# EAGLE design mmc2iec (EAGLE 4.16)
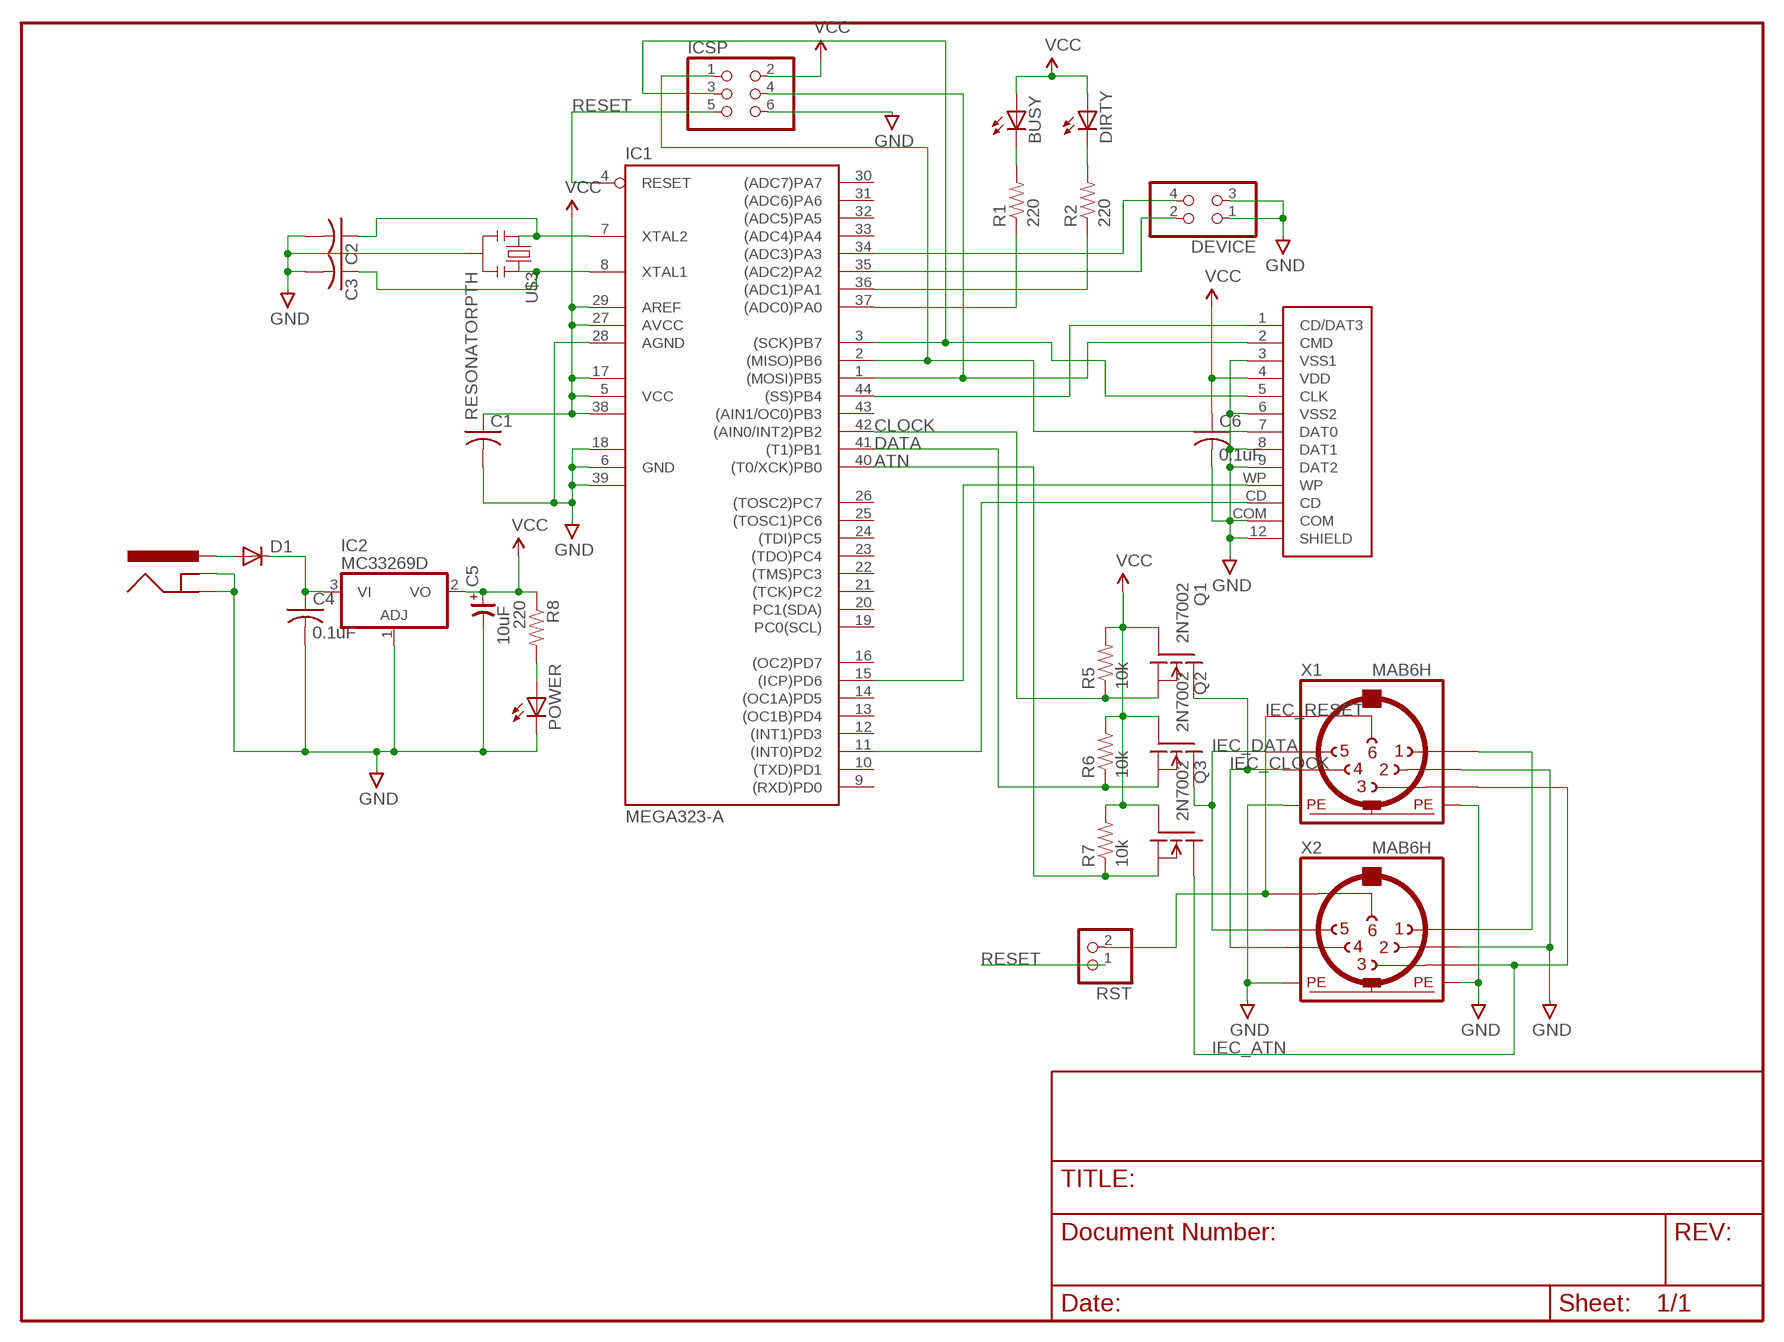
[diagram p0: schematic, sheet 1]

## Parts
BUSY  LED1206  [LED-1206]
C1  C-USC1206  [C1206]
C2  C-USC1206  [C1206]
C3  C-USC1206  [C1206]
C4  0.1uF  C-USC1206  [C1206]
C5  10uF  CP-SV-B  [SV-B]
C6  0.1uF  C-USC1206  [C1206]
D1  DIODESMA  [SMA-DIODE]
DC_IN  POWER_JACKPTH  [POWER_JACK_PTH]
DEVICE  PINHD-2X2  [2X02]
DIRTY  LED1206  [LED-1206]
IC1  MEGA323-A  [TQFP44]
IC2  MC33269D  [DPACK]
ICSP  PINHD-2X3  [2X03]
POWER  LED1206  [LED-1206]
Q1  2N7002  [SOT23]
Q2  2N7002  [SOT23]
Q3  2N7002  [SOT23]
R1  220  RESISTOR1206  [1206]
R2  220  RESISTOR1206  [1206]
R5  10k  RESISTOR1206  [1206]
R6  10k  RESISTOR1206  [1206]
R7  10k  RESISTOR1206  [1206]
R8  220  RESISTOR1206  [1206]
RST  PINHD-1X2  [1X02]
SDCARD  SDCARD_SOCKET_TK  [SD-MMC_SOCKET-PP]
U$3  RESONATORPTH  [RESONATOR-PTH]
X1  MAB6H  [MAB6H]
X2  MAB6H  [MAB6H]

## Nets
ATN: IC1.40((T0/XCK)PB0) Q3.2(S) R7.1
CLOCK: IC1.42((AIN0/INT2)PB2) Q1.2(S) R5.1
DATA: IC1.41((T1)PB1) Q2.2(S) R6.1
GND [POWER]: C1.2 C2.2 C3.2 C4.2 C5.- C6.2 DC_IN.GND DC_IN.GNDBREAK DEVICE.1 DEVICE.3 IC1.6(GND) IC1.18(GND1) IC1.28(AGND) IC1.39(GND2) IC2.1(ADJ) ICSP.6 POWER.C SDCARD.3(VSS1) SDCARD.6(VSS2) SDCARD.8(DAT1) SDCARD.9(DAT2) SDCARD.12(SHIELD) SDCARD.COM U$3.2 X1.2 X1.PE X1.PE@(PE) X2.2 X2.PE X2.PE@(PE)
IEC_ATN: Q3.3(D) X1.3 X2.3
IEC_CLOCK: Q1.3(D) X1.4 X2.4
IEC_DATA: Q2.3(D) X1.5 X2.5
IEC_RESET: RST.2 X1.6 X2.6
N$1: C2.1 IC1.7(XTAL2) U$3.1
N$2: C3.1 IC1.8(XTAL1) U$3.3
N$6: IC1.44((SS)PB4) SDCARD.1(CD/DAT3)
N$7: IC1.1((MOSI)PB5) ICSP.4 SDCARD.2(CMD)
N$8 [POWER]: D1.A DC_IN.PWR
N$9: IC1.3((SCK)PB7) ICSP.3 SDCARD.5(CLK)
N$10: IC1.2((MISO)PB6) ICSP.1 SDCARD.7(DAT0)
N$11: IC1.11((INT0)PD2) SDCARD.CD
N$12: IC1.15((ICP)PD6) SDCARD.WP
N$13: IC1.37((ADC0)PA0) R1.1
N$14: IC1.36((ADC1)PA1) R2.1
N$15: BUSY.C R1.2
N$16: DIRTY.C R2.2
N$19: DEVICE.2 IC1.35((ADC2)PA2)
N$20: DEVICE.4 IC1.34((ADC3)PA3)
N$21: POWER.A R8.2
N$28: X1.1 X2.1
N$31 [POWER]: C4.1 D1.C IC2.3(VI)
RESET: IC1.4(RESET) ICSP.5 RST.1
VCC [POWER]: BUSY.A C1.1 C5.+ C6.1 DIRTY.A IC1.5(VCC) IC1.17(VCC1) IC1.27(AVCC) IC1.29(AREF) IC1.38(VCC2) IC2.2(VO) ICSP.2 Q1.1(G) Q2.1(G) Q3.1(G) R5.2 R6.2 R7.2 R8.1 SDCARD.4(VDD)
Unconnected: IC1.9((RXD)PD0) IC1.10((TXD)PD1) IC1.12((INT1)PD3) IC1.13((OC1B)PD4) IC1.14((OC1A)PD5) IC1.16((OC2)PD7) IC1.19(PC0(SCL)) IC1.20(PC1(SDA)) IC1.21((TCK)PC2) IC1.22((TMS)PC3) IC1.23((TDO)PC4) IC1.24((TDI)PC5) IC1.25((TOSC1)PC6) IC1.26((TOSC2)PC7) IC1.30((ADC7)PA7) IC1.31((ADC6)PA6) IC1.32((ADC5)PA5) IC1.33((ADC4)PA4) IC1.43((AIN1/OC0)PB3)

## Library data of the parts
BUSY DIRTY POWER = SparkFunEagle-6-6-07:LED: LEDs
C1-C4 C6 = rcl:C-US: CAPACITOR, American symbol
C5 = cap-master:CP-: POLARIZED CAP
D1 = SparkFunEagle-6-6-07:DIODE: Diode
DC_IN = SparkFunEagle-6-6-07:POWER_JACK: Power Jack This is the standard 5.5mm barrel jack for power. The PTH is the most common, proven, reliable, footprint. All others are experimental. The Slot footprint only works if the mill layer is transmitted to the PCB fab house so be warned. Spark Fun Electronics SKU : PRT-00119. Mating wall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
DEVICE = pinhead:PINHD-2X2: PIN HEADER
IC1 = atmel:MEGA323: MICROCONTROLLER 32 Kbytes FLASH 2 Kbytes SRAM 1 Kbytes EEPROM USART 8-channel 10 bit ADC Source: avr.lbr
IC2 = linear3:MC33269?*: Adjustable Output Low Dropout Voltage Regulator 800 mA Source: http://www.onsemi.com/pub/Collateral/MC33269-D.PDF
ICSP = pinhead:PINHD-2X3: PIN HEADER
Q1-Q3 = transistors_gaui:2N7002
R1 R2 R5-R8 = SparkFunEagle-6-6-07:RESISTOR: Resistor
RST = pinhead:PINHD-1X2: PIN HEADER
SDCARD = SparkFunEagle-6-6-07:SDCARD_SOCKET_TK
U$3 = SparkFunEagle-6-6-07:RESONATOR: Resonator Small SMD resonator. This is the itty bitty 10/20MHz resonators with built in caps. CSTCE10M0G55 and CSTCE20M0V53. Footprint has been reviewed closely but hasn't been tested yet.
X1 X2 = con-hirschmann:MAB6H: Female CONNECTOR 6 pins with shield, horizontal (DIN 45322)

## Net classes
0 default: width 0.178 mm
1 POWER: width 0.254 mm

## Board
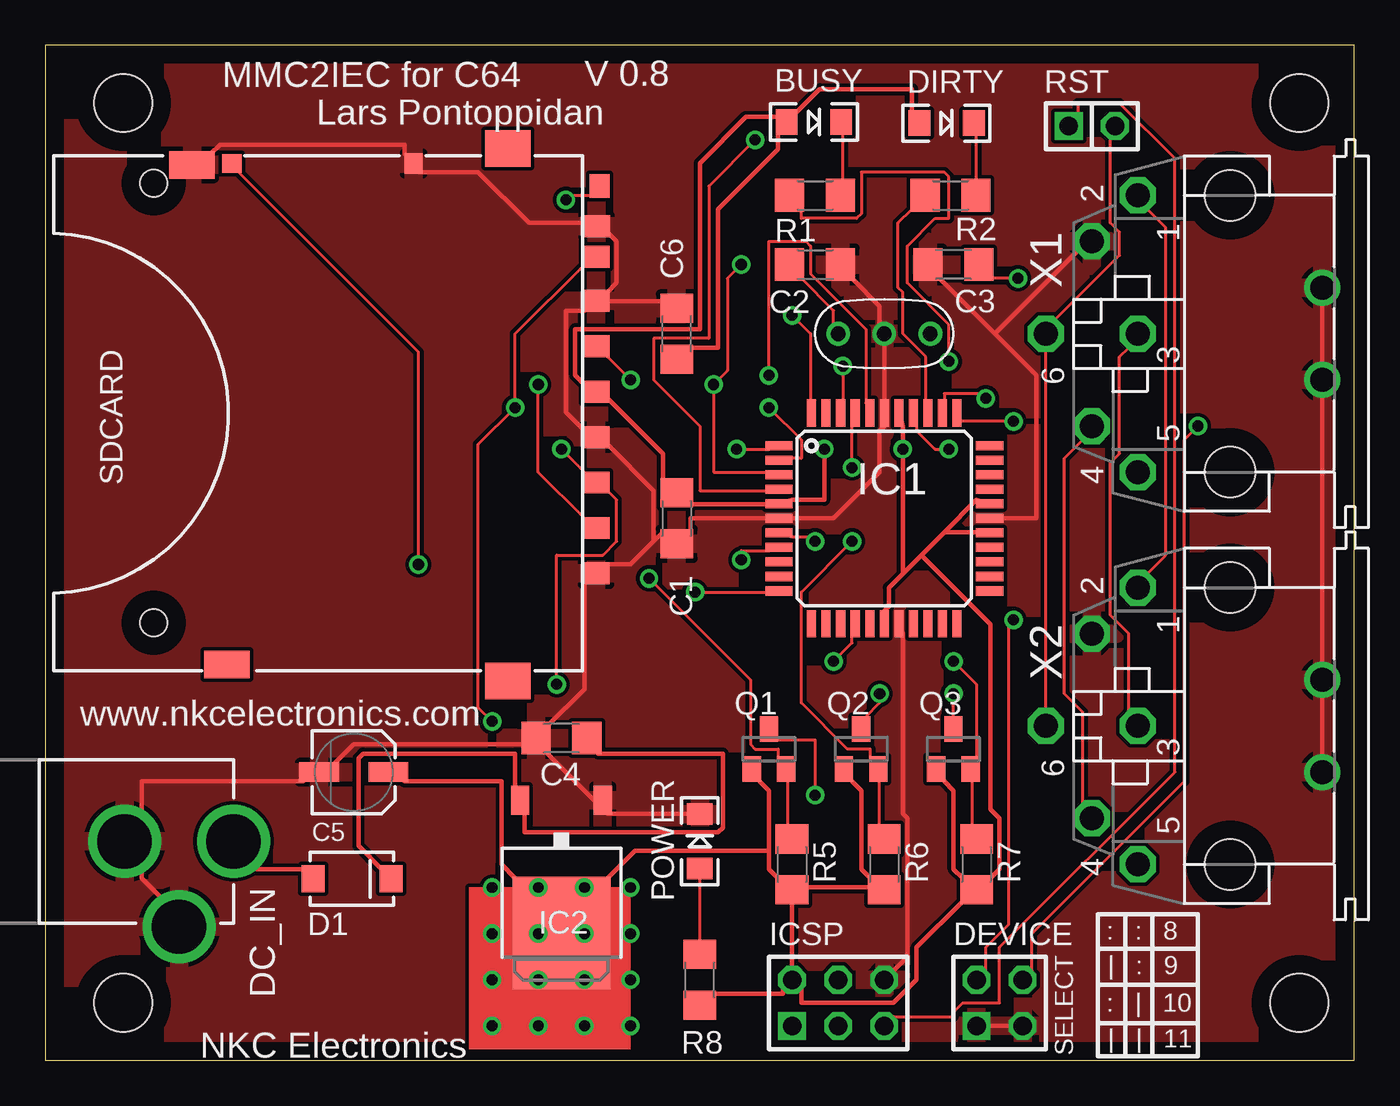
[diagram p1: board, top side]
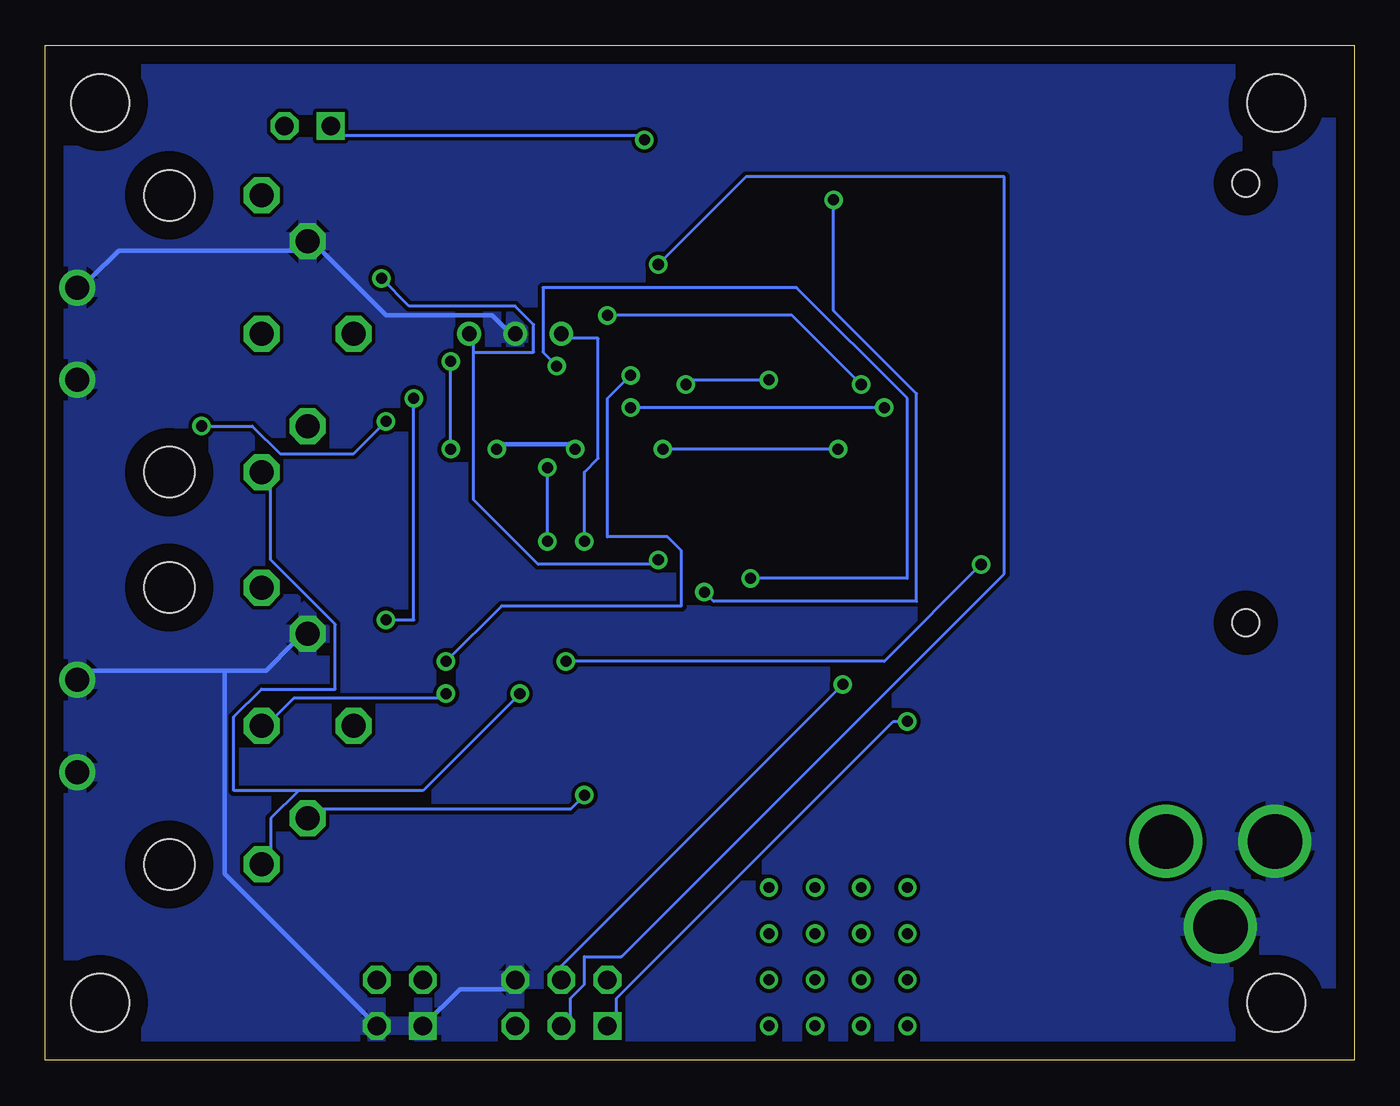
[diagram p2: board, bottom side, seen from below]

Size 72.06 x 55.87 mm. Coordinates in mm from the lower left corner, seen from the top.
Outline: 0,0 72.06,0 72.06,55.87 0,55.87 0,0
Copper layers (1*16): Top 0.035mm / dielectric 1.5mm / Bottom 0.035mm
Design rules "default": minimum track width 7mil, minimum drill 24mil, track to track 8mil, track to pad 8mil, pad to pad 8mil, via to via 24mil, smd to smd 8mil, copper to edge 40mil, drill to drill 8mil, minimum pad ring 10mil, minimum via ring 8mil, stop-mask expansion 4mil, vias tented up to drill 0mil, thermal gap 10mil
Holes 3.2 mm at 4.28,52.7 69.05,52.7 4.28,3.17 69.05,3.17

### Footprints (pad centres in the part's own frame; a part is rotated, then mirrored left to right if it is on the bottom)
LED-1206 = smd 1.2 x 1.4: A -1.5,0; C 1.5,0
C1206 = smd 1.6 x 1.8: 1 -1.4,0; 2 1.4,0
SV-B = smd 2.184 x 1.067: + -1.905,0; - 1.905,0
SMA-DIODE = smd 1.27 x 1.47: A -2.15,0; C 2.15,0
POWER_JACK_PTH = drill 2.997 round: GND 0,7.7; GNDBREAK 4.7,10.7; PWR 0,13.7
2X02 = drill 1.016 square: 1 -1.27,-1.27 | drill 1.016 octagon: 2 -1.27,1.27; 3 1.27,-1.27; 4 1.27,1.27
TQFP44 = smd 1.5 x 0.5: 1 -5.8,4; 2 -5.8,3.2; 3 -5.8,2.4; 4 -5.8,1.6; 5 -5.8,0.8; 6 -5.8,0; 7 -5.8,-0.8; 8 -5.8,-1.6; 9 -5.8,-2.4; 10 -5.8,-3.2; 11 -5.8,-4; 23 5.8,-4; 24 5.8,-3.2; 25 5.8,-2.4; 26 5.8,-1.6; 27 5.8,-0.8; 28 5.8,0; 29 5.8,0.8; 30 5.8,1.6; 31 5.8,2.4; 32 5.8,3.2; 33 5.8,4 | smd 0.5 x 1.5: 12 -4,-5.8; 13 -3.2,-5.8; 14 -2.4,-5.8; 15 -1.6,-5.8; 16 -0.8,-5.8; 17 0,-5.8; 18 0.8,-5.8; 19 1.6,-5.8; 20 2.4,-5.8; 21 3.2,-5.8; 22 4,-5.8; 34 4,5.8; 35 3.2,5.8; 36 2.4,5.8; 37 1.6,5.8; 38 0.8,5.8; 39 0,5.8; 40 -0.8,5.8; 41 -1.6,5.8; 42 -2.4,5.8; 43 -3.2,5.8; 44 -4,5.8
DPACK = smd 1 x 1.6: 1 -2.28,-4.8; 3 2.28,-4.8 | smd 5.4 x 6.2: 2 0,2.5
2X03 = drill 1.016 square: 1 -2.54,-1.27 | drill 1.016 octagon: 2 -2.54,1.27; 3 0,-1.27; 4 0,1.27; 5 2.54,-1.27; 6 2.54,1.27
SOT23 = smd 1 x 1.4: 1 -0.95,-1.1; 2 0.95,-1.1; 3 0,1.1
1206 = smd 1.6 x 1.8: 1 -1.4,0; 2 1.4,0
1X02 = drill 1.016 square: 1 -1.27,0 | drill 1.016 octagon: 2 1.27,0
SD-MMC_SOCKET-PP = smd 1.2 x 1.5: 1 6.88,29.85; 2 4.38,29.85; 3 1.88,29.85; 4 -0.62,29.85; 5 -3.12,29.85; 6 -5.62,29.85; 7 -8.04,29.85; 8 -9.728,29.87; 9 9.38,29.85 | smd 1.5 x 2.5: 12 -13.1,7.6; 13 14.402,9.525 | smd 2 x 2.5: 14 -14,25; 15 15.3,25 | smd 1.3 x 1.1: CD -11.938,30.048 | smd 1.15 x 1: COM -13.18,19.8 | smd 1 x 1.05: WP -13.18,9.8 | hole 1.5: -12.1,5.5; 12.1,5.5
RESONATOR-PTH = drill 0.8 round: 1 -2.54,0; 2 0,0; 3 2.54,0
MAB6H = drill 1.321 octagon: 1 7.62,5.08; 2 5.08,7.62; 3 0,5.08; 4 -5.08,7.62; 5 -7.62,5.08; 6 0,10.16 | drill 1.321 round: PE -2.54,-5.08; PE@ 2.54,-5.08 | hole 2.794: 7.62,0; -7.62,0

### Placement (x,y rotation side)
BUSY  42.32,51.65 0 top
C1  34.76,29.84 270 top
C2  42.38,43.81 0 top
C3  50,43.81 180 top
C4  28.41,17.74 180 top
C5  16.98,15.87 180 top
C6  34.76,40 90 top
D1  16.88,10 0 top
DC_IN  -3.34,12.06 270 top
DEVICE  52.54,3.17 0 top
DIRTY  49.62,51.59 0 top
IC1  46.19,29.84 0 top
IC2  28.41,9.52 180 top
ICSP  43.65,3.17 0 top
POWER  36.03,12.06 90 top
Q1  39.84,17.14 0 top
Q2  44.92,17.14 0 top
Q3  50,17.14 0 top
R1  42.38,47.62 0 top
R2  49.84,47.62 0 top
R5  41.11,10.79 270 top
R6  46.19,10.79 270 top
R7  51.27,10.79 270 top
R8  36.03,4.44 90 top
RST  57.62,51.43 0 top
SDCARD  0.47,36.19 270 top
U$3  46.19,40 0 top
X1  65.24,40 90 top
X2  65.24,18.41 90 top

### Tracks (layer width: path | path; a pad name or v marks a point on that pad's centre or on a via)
ATN  (via drill 0.61)
  Top 0.178: R7.1 51.02,12.82 51.02,15.36 Q3.2 51.27,16.63 51.27,20.7 v50,21.97 | v39.84,37.71 39.84,45.08 41.87,45.08 42.13,44.83 42.13,43.3 45.17,40.25 45.17,36.19 IC1.40
  Bottom 0.178: v39.84,37.71 41.11,36.44 41.11,28.82 37.81,28.82 37.05,28.06 37.05,25.01 46.95,25.01 v50,21.97
CLOCK  (via drill 0.61)
  Top 0.178: R5.1 40.86,12.82 40.86,15.36 Q1.2 40.35,16.63 40.35,17.14 39.08,17.14 38.82,17.39 38.82,20.95 v33.24,26.54 | v43.9,38.22 43.9,36.19 IC1.42
  Bottom 0.178: v43.9,38.22 44.67,38.98 44.67,42.54 30.7,42.54 24.6,36.44 24.6,26.54 v33.24,26.54
DATA  (via drill 0.61)
  Top 0.178: R6.1 45.94,12.82 45.94,15.36 Q2.2 45.43,16.63 45.43,17.14 44.16,17.14 41.62,19.68 41.62,25.78 v44.41,28.57 | v44.41,32.63 44.41,34.92 IC1.41
  Bottom 0.178: v44.41,28.57 v44.41,32.63
GND
  Top 0.254: DEVICE.3 DEVICE.1 | IC1.18 47.21,23.49 47.21,13.58 47.46,13.33 47.46,5.71 ICSP.6 | X2.PE X2.PE@ X1.PE X1.PE@ | 52.29,40 49.24,43.05 C3.2 | 52.29,40 54.57,37.71 54.57,29.84 IC1.28 | 52.29,40 56.86,44.57 X1.2 | SDCARD.6 30.95,41.78 34,41.78 C6.2 | SDCARD.12 9.11,49.91 9.61,50.41 19.77,50.41 19.77,49.91 SDCARD.COM 20.54,48.89 23.84,48.89 26.63,46.1 29.68,46.1 SDCARD.8 30.95,45.59 31.46,45.08 31.46,42.79 30.95,42.29 SDCARD.6 | DC_IN.GNDBREAK 6.31,9.01 5.3,10.03 5.3,10.28 DC_IN.GND 5.3,13.84 5.3,15.36 14.19,15.36 C5.- 15.96,16.38 16.98,17.39 26.38,17.39 C4.2 | POWER.C 35.52,13.58 30.95,13.58 IC2.1 30.44,14.09 27.65,16.89 C4.2 | C2.2 44.41,43.05 45.94,41.52 45.94,40.51 U$3.2 IC1.39 46.19,34.92 45.94,34.67 45.94,32.38 43.4,29.84 IC1.6 35.52,29.84 35.52,29.08 C1.2 34,29.08 33.49,28.57 | 33.49,28.57 32.22,27.3 30.95,27.3 SDCARD.9 29.68,26.28 29.68,20.44 27.65,18.41 C4.2 | 33.49,28.57 33.49,31.36 30.95,33.9 SDCARD.3 29.68,34.67 28.66,35.68 28.66,41.27 29.68,41.27 SDCARD.6
  Bottom 0.254: DEVICE.1 49.24,3.93 46.7,3.93 ICSP.6 | 62.19,21.46 69.56,21.46 X2.PE@ | 62.19,21.46 59.91,21.46 58.38,22.98 X2.2 | X1.PE@ 69.56,43.05 68.03,44.57 58.38,44.57 X1.2 56.86,44.57 53.3,41.02 47.46,41.02 46.7,40.25 U$3.2 | 62.19,21.46 62.19,10.28 DEVICE.3
  pour Top: -0.8,-0.64 72.86,-0.64 72.86,56.51 -0.8,56.51
  pour Bottom: -0.8,-0.64 72.86,-0.64 72.86,56.51 -0.8,56.51
IEC_ATN  (via drill 0.61)
  Top 0.178: Q3.3 v50,20.19 | X1.3 59.65,39.24 59.14,38.73 59.14,33.4 58.64,32.89 58.64,24.51 59.65,23.49 59.65,19.17 X2.3
  Bottom 0.178: v50,20.19 50.25,19.93 58.38,19.93 59.4,18.92 X2.3
IEC_CLOCK  (via drill 0.61)
  Top 0.178: v42.38,14.6 42.38,17.65 40.09,17.65 Q1.3 | X1.4 57.11,34.16 56.1,33.14 56.1,20.19 57.11,19.17 57.11,14.09 X2.4
  Bottom 0.178: v42.38,14.6 43.14,13.84 56.86,13.84 X2.4
IEC_DATA  (via drill 0.61)
  Top 0.178: v45.94,20.19 45.94,19.68 45.17,18.92 Q2.3
  Bottom 0.178: v45.94,20.19 51.27,14.85 58.13,14.85 | 58.13,14.85 59.65,13.33 59.65,11.55 X2.5 | 58.13,14.85 61.68,14.85 61.68,18.92 60.16,20.44 56.1,20.44 56.1,24 59.65,27.55 59.65,31.62 X1.5
IEC_RESET
  Top 0.178: RST.2 58.64,50.92 58.64,46.1 59.14,45.59 59.14,44.32 55.59,40.76 X1.6 X2.6
N$1  (via drill 0.61)
  Top 0.178: v42.38,28.57 42.38,28.82 41.11,28.82 IC1.7 | C2.1 41.62,43.05 43.4,41.27 43.4,40.51 U$3.1
  Bottom 0.178: v42.38,28.57 42.38,32.38 41.62,33.14 41.62,39.75 43.14,39.75 U$3.1
N$2  (via drill 0.61)
  Top 0.178: v38.32,27.55 38.32,28.06 39.84,28.06 IC1.8 | v53.56,43.05 52.03,43.05 C3.1
  Bottom 0.178: v38.32,27.55 38.57,27.3 44.92,27.3 48.48,30.86 48.48,38.98 | 48.48,38.98 48.48,39.49 U$3.3 | v53.56,43.05 52.03,41.52 46.19,41.52 45.17,40.51 45.17,38.98 48.48,38.98
N$6  (via drill 0.61)
  Top 0.178: v27.14,37.21 27.14,32.38 29.68,29.84 SDCARD.1 | v41.11,41.02 42.13,40 42.13,36.19 IC1.44
  Bottom 0.178: v27.14,37.21 30.95,41.02 v41.11,41.02
N$7  (via drill 0.61)
  Top 0.178: v28.16,20.7 28.16,27.81 30.7,27.81 31.46,28.57 31.46,30.86 30.95,31.36 SDCARD.2 29.68,32.38 v28.41,33.65 | v38.06,33.65 39.84,33.65 IC1.1
  Bottom 0.178: v28.16,20.7 43.9,4.95 ICSP.4 | v28.41,33.65 v38.06,33.65
N$8
  Top 0.254: D1.A 14.19,10.54 11.65,10.54 DC_IN.PWR
N$9  (via drill 0.61)
  Top 0.178: v32.22,37.46 30.95,38.73 SDCARD.5 | IC1.3 39.84,32.38 36.79,32.38 v36.79,37.21 37.55,37.97 37.55,43.05 v38.32,43.81
  Bottom 0.178: v36.79,37.21 36.54,37.46 v32.22,37.46 | v38.32,43.81 33.49,48.64 19.27,48.64 19.27,26.79 40.35,5.71 42.38,5.71 42.38,4.19 43.14,3.42 43.14,2.41 ICSP.3
N$10  (via drill 0.61)
  Top 0.178: v39.84,35.94 41.62,34.16 41.62,33.14 41.11,33.14 IC1.2 | SDCARD.7 29.68,43.81 25.87,40 v25.87,35.94 23.84,33.9 23.84,19.43 v24.6,18.66
  Bottom 0.178: v25.87,35.94 v39.84,35.94 | v24.6,18.66 25.36,18.66 40.6,3.42 40.6,2.41 ICSP.1
N$11  (via drill 0.61)
  Top 0.178: v28.66,47.37 28.66,47.62 30.19,47.62 SDCARD.CD | v35.78,25.78 39.84,25.78 IC1.11
  Bottom 0.178: v28.66,47.37 28.66,41.27 24.09,36.7 24.09,25.27 35.27,25.27 v35.78,25.78
N$12  (via drill 0.61)
  Top 0.178: v20.54,27.3 20.54,38.98 10.63,48.89 SDCARD.WP | v43.4,21.97 44.41,22.98 44.41,23.49 IC1.15
  Bottom 0.178: v20.54,27.3 25.87,21.97 v43.4,21.97
N$13  (via drill 0.61)
  Top 0.178: v49.75,33.65 48.98,33.65 47.97,34.67 47.97,34.92 IC1.37 | v49.75,38.48 49.75,40.51 47.46,42.79 47.46,44.83 48.98,46.35 49.75,46.35 49.75,48.64 49.49,48.89 44.92,48.89 44.92,46.6 44.67,46.35 41.62,46.35 41.62,46.86 R1.1
  Bottom 0.178: v49.75,33.65 v49.75,38.48
N$14
  Top 0.178: IC1.36 48.48,36.19 48.48,38.73 47.21,40 47.21,42.29 46.95,42.54 46.95,46.1 47.71,46.86 R2.1
N$15
  Top 0.178: BUSY.C 43.9,51.18 43.9,48.38 R1.2
N$16
  Top 0.178: DIRTY.C 51.27,50.92 51.27,48.38 R2.2
N$17  (via drill 0.6)
  other vias: 24.6,1.9
N$19  (via drill 0.61)
  Top 0.178: v51.78,36.44 51.78,36.7 49.49,36.7 49.49,36.19 IC1.35 | v53.3,24.25 53.05,24 53.05,7.49 51.78,6.22 51.78,4.95 DEVICE.2
  Bottom 0.178: v51.78,36.44 51.78,24.25 v53.3,24.25
N$20  (via drill 0.61)
  Top 0.178: v53.3,35.17 50.25,35.17 IC1.34 | v63.46,34.92 62.7,34.16 62.7,15.36 54.32,6.98 54.32,4.95 DEVICE.4
  Bottom 0.178: v53.3,35.17 55.08,33.4 59.14,33.4 60.67,34.92 v63.46,34.92
N$21
  Top 0.178: R8.2 POWER.A
N$22  (via drill 0.6)
  other vias: 27.14,1.9
N$23  (via drill 0.6)
  other vias: 29.68,1.9
N$24  (via drill 0.6)
  other vias: 32.22,1.9
N$25  (via drill 0.6)
  other vias: 32.22,4.44
N$26  (via drill 0.6)
  other vias: 29.68,4.44
N$27  (via drill 0.6)
  other vias: 27.14,4.44
N$28
  Top 0.178: X2.1 60.67,26.79 61.68,27.81 61.68,45.84 60.67,46.86 X1.1
N$29  (via drill 0.6)
  other vias: 24.6,4.44
N$30  (via drill 0.6)
  other vias: 24.6,6.98
N$31
  Top 0.254: D1.C 18.5,10.54 17.23,11.81 17.23,16.63 17.49,16.89 25.87,16.89 25.87,15.11 IC2.3 26.38,13.58 26.38,12.57 37.05,12.57 37.3,12.82 37.3,16.89 30.44,16.89 C4.1
N$32  (via drill 0.6)
  other vias: 27.14,6.98
N$33  (via drill 0.6)
  other vias: 29.68,6.98
N$34  (via drill 0.6)
  other vias: 32.22,6.98
N$35  (via drill 0.6)
  other vias: 32.22,9.52
N$36  (via drill 0.6)
  other vias: 29.68,9.52
N$37  (via drill 0.6)
  other vias: 27.14,9.52
N$38  (via drill 0.6)
  other vias: 24.6,9.52
RESET  (via drill 0.61)
  Top 0.178: v39.08,50.67 36.54,48.13 36.54,39.75 33.49,39.75 33.49,37.46 36.03,34.92 36.03,31.36 39.84,31.36 IC1.4 | ICSP.5 46.7,2.41 50,2.41 50,2.66 50.51,3.17 52.54,3.17 52.54,6.22 62.19,15.87 62.19,49.65 59.14,52.7 56.86,52.7 56.86,51.94 RST.1
  Bottom 0.178: v39.08,50.67 39.33,50.92 55.84,50.92 RST.1
VCC  (via drill 0.61)
  Top 0.254: BUSY.A 41.36,52.19 42.63,53.46 47.71,53.46 47.71,52.19 DIRTY.A | C6.1 35.52,39.24 37.05,39.24 37.05,46.86 40.35,50.16 40.35,51.18 BUSY.A | BUSY.A 40.35,51.94 38.57,51.94 36.03,49.4 36.03,40.25 29.17,40.25 29.17,37.71 29.68,37.21 SDCARD.4 30.95,36.44 34,33.4 34,31.87 C1.1 35.52,30.6 39.84,30.6 IC1.5 41.11,30.86 42.89,30.86 v42.89,33.65 | C5.+ 19.77,15.36 25.11,15.36 25.11,10.79 25.87,10.03 IC2.2 30.95,10.03 32.47,11.55 39.84,11.55 | 49.49,29.08 51.27,30.86 IC1.29 | 48.22,27.81 49.49,29.08 | 48.22,27.81 47.21,26.79 | 47.21,26.79 46.44,26.03 46.44,25.01 46.19,24.76 IC1.17 | 49.49,29.08 51.27,29.08 IC1.27 | 47.21,26.79 v47.21,33.65 47.21,34.92 IC1.38 | 39.84,11.55 39.84,10.54 40.35,10.03 R5.2 | 39.84,11.55 39.84,14.85 39.33,15.36 Q1.1 | Q2.1 44.41,15.36 44.92,14.85 44.92,10.54 45.43,10.03 R6.2 45.43,9.52 41.87,9.52 R5.2 | Q3.1 49.49,15.36 50,14.85 50,10.54 50.51,10.03 R7.2 | R8.1 36.79,3.68 40.6,3.68 40.6,3.93 ICSP.2 | R7.2 50.51,8.76 47.97,6.22 47.97,4.44 46.7,3.17 41.62,3.17 41.62,3.93 ICSP.2 | R5.2 ICSP.2 | 48.22,27.81 52.03,24 52.03,13.84 52.54,13.33 52.54,10.54 52.03,10.03 R7.2
  Bottom 0.254: v42.89,33.65 43.14,33.9 46.95,33.9 v47.21,33.65
(copper drawn outside any net)
  shapes: Top area x1

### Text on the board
tPlace: MMC2IEC for C64 | V 0.8 | Lars Pontoppidan | www.nkcelectronics.com | : : 8 | | : 9 | : | 10 | NKC Electronics | SELECT | | | 11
